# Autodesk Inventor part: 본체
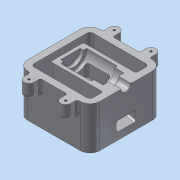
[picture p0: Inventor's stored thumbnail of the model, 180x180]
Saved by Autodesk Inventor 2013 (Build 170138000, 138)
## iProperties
Created: 2018-01
Part Number: 본체
Material: 알루미늄 6061
Document SubType Name: Modeling
Designer: dgall
Density: 2.71 g/cm^3
Mass: 1008.2 g
Surface Area: 833.849 cm^2
Volume: 372.03 cm^3
Author: dgall
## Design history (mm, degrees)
sketch "스케치1"
  geometry: L1 (-55, -55)-(55, -55); L2 (55, -55)-(55, 55); L3 (55, 55)-(-55, 55); L4 (-55, 55)-(-55, -55); L5 (-45, -45)-(45, -45); L6 (45, -45)-(45, 45); L7 (45, 45)-(-45, 45); L8 (-45, 45)-(-45, -45); 5 further points
  constraints: 16 end point, 4 midpoint, 4 parallel, 2 horizontal, 2 horizontal alignment, 2 perpendicular, 2 vertical alignment
  dimensions: "d0" = 110 distance of L2.end L3.end; "d2" = 110 distance of L1.end L2.end; "d3" = 10 distance between parallel lines of L3 L7; "d4" = 10 distance between parallel lines of L2 L6
extrude "돌출1" new body sketch "스케치1" distance "d5" = 65; taper "d6" = 0 deg
fillet "모깎기1" dims "d7" = 15, "d8" = 5
sketch "스케치2"
  geometry: L1 (40, 55)-(-40, 55) reference; L2 (-55, 40)-(-55, -40) reference; L3 (40, -45)-(-40, -45) reference; L4 (-35.5, 55)-(-35.5, 65); L5 (-20.5, 65)-(-20.5, 55); L6 (20.5, 55)-(20.5, 65); L7 (35.5, 65)-(35.5, 55); A1 r 7.5 centre (-28, 65) between (-20.5, 65) and (-35.5, 65); A2 r 7.5 centre (28, 65) between (35.5, 65) and (20.5, 65); 1 further point
  constraints: 8 end point, 4 point on circle, 4 point on line, 3 parallel, 3 perpendicular, 2 centre point, 2 tangent
  dimensions: "d13" = 27 distance from line of L2 A1.centre; "d14" = 15 diameter of A1; "d15" = 10 distance from line of L1 A1.centre; "d16" = 15 diameter of A2; "d17" = 56 distance of A1.centre A2.centre; "d18" = 10 distance from line of L1 A2.centre
extrude "돌출2" join sketch "스케치2" distance "d19" = 20; taper "d20" = 0 deg
fillet "모깎기4" dims "d23" = 3
fillet "모깎기5" dims "d24" = 3
sketch "스케치3"
  geometry: L1 (-55, 0)-(-55, 65) reference; L2 (-45, 65)-(-45, 0) reference; L3 (-45, 8.564)-(35, 30); L4 (-40, 0)-(-40, 65) reference; L5 (40, 0)-(-40, 0) reference; L6 (40, 65)-(40, 0) reference; L7 (-40, 65)-(40, 65) reference; L8 (35, 30)-(35, 65); L9 (35, 65)-(-55, 65); L10 (55, 65)-(55, 0) reference; L11 (-55, 65)-(-55, 8.564); L12 (-45, 8.564)-(-55, 8.564); 1 further point
  constraints: 10 end point, 3 perpendicular, 3 point on line
  dimensions: "d25" = 105 deg angle of L2 L3; "d26" = 30 distance from line of L5 L3.end; "d27" = 20 distance between parallel lines of L10 L8
extrude "돌출3" join sketch "스케치3" stored distance "d28" = 50; taper "d29" = 0 deg
sketch "스케치4"
  geometry: L1 (-55, 65)-(-40, 65) reference; L2 (-55, 65)-(-55, 57.5); L3 (-55, 57.5)-(-36, 57.5); L4 (-36, 57.5)-(-36, 49); L5 (-36, 49)-(-22, 49); L6 (-22, 49)-(-22, 45); L7 (-22, 45)-(25, 45); L8 (25, 45)-(25, 50); L9 (35, 65)-(-55, 65); L10 (25, 50)-(30, 50); L11 (30, 50)-(30, 65); 2 further points
  constraints: 20 end point, 6 parallel, 3 perpendicular, 1 collinear, 1 point on line, 1 vertical alignment
  dimensions: "d30" = 15 diameter of L3 L9; "d32" = 19 distance from line of L3.end L2; "d33" = 14 distance between parallel lines of L6 L4; "d34" = 32 diameter of L5 L9; "d35" = 40 diameter of L7 L9; "d37" = 47 distance between parallel lines of L8 L6; "d38" = 5 distance between parallel lines of L8 L11; "d39" = 30 diameter of L10 L9
revolve "회전1" sketch "스케치4" stored, may be unused: angle "d40" = 90 deg
sketch "스케치5"
  geometry: L1 (-55, 0)-(-55, 65) reference; L2 (-22, 45)-(25, 45) reference; L3 (35, 30)-(-45, 8.564) reference; L4 (-55, 26.061)-(-17, 36.243); L5 (-55, 11.061)-(20, 31.157); L6 (-22, 65)-(25, 65) reference; L7 (-17, 36.243)-(-17, 65); L8 (20, 31.157)-(20, 65); L9 (-22, 45)-(-22, 65) reference; 1 further point
  constraints: 8 end point, 4 point on line, 2 perpendicular, 1 parallel
  dimensions: "d41" = 5 distance between parallel lines of L3 L5; "d42" = 75 deg angle of L1 L4; "d43" = 15 distance of L5.start L4.start; "d45" = 5 distance between parallel lines of L9 L7; "d46" = 37 distance between parallel lines of L8 L7
extrude "돌출4" cut sketch "스케치5" stored distance "d47" = 30; taper "d48" = 0 deg
chamfer "모따기1" distance "d49" = 1; stored, may be unused: second distance "d50" = 2, angle "d51" = 45 deg
fillet "모깎기6" dims "d52" = 1
fillet "모깎기7" dims "d53" = 3
fillet "모깎기8" dims "d54" = 3
fillet "모깎기9" dims "d55" = 3
fillet "모깎기10" dims "d56" = 3
fillet "모깎기11" dims "d57" = 3
hole "구멍1" diameter "d60" = 3.242; stored, may be unused: countersink angle "d64" = 90 deg, drill point angle "d66" = 118 deg; dims "d58" = 10, "d59" = 10, "d61" = 9, "d62" = 4, "d63" = 2, "d65" = 11
sketch "스케치6"
  geometry: L1 (80, 0)-(0, 0) reference; 3 further points
  constraints: 1 midpoint, 1 vertical alignment, 1 other
  dimensions: "d67" = 20 distance of point (40, 0) point (40, -20)
feature "엠보싱1" sketch "스케치6" dims "d0" = 110, "d2" = 110, "d3" = 10, "d4" = 10, "d68" = 0.5, "d69" = 0
node "솔리드1"
mirror "대칭1"
mirror "대칭2"
mirror "대칭3"
node "투영된 루프1"
